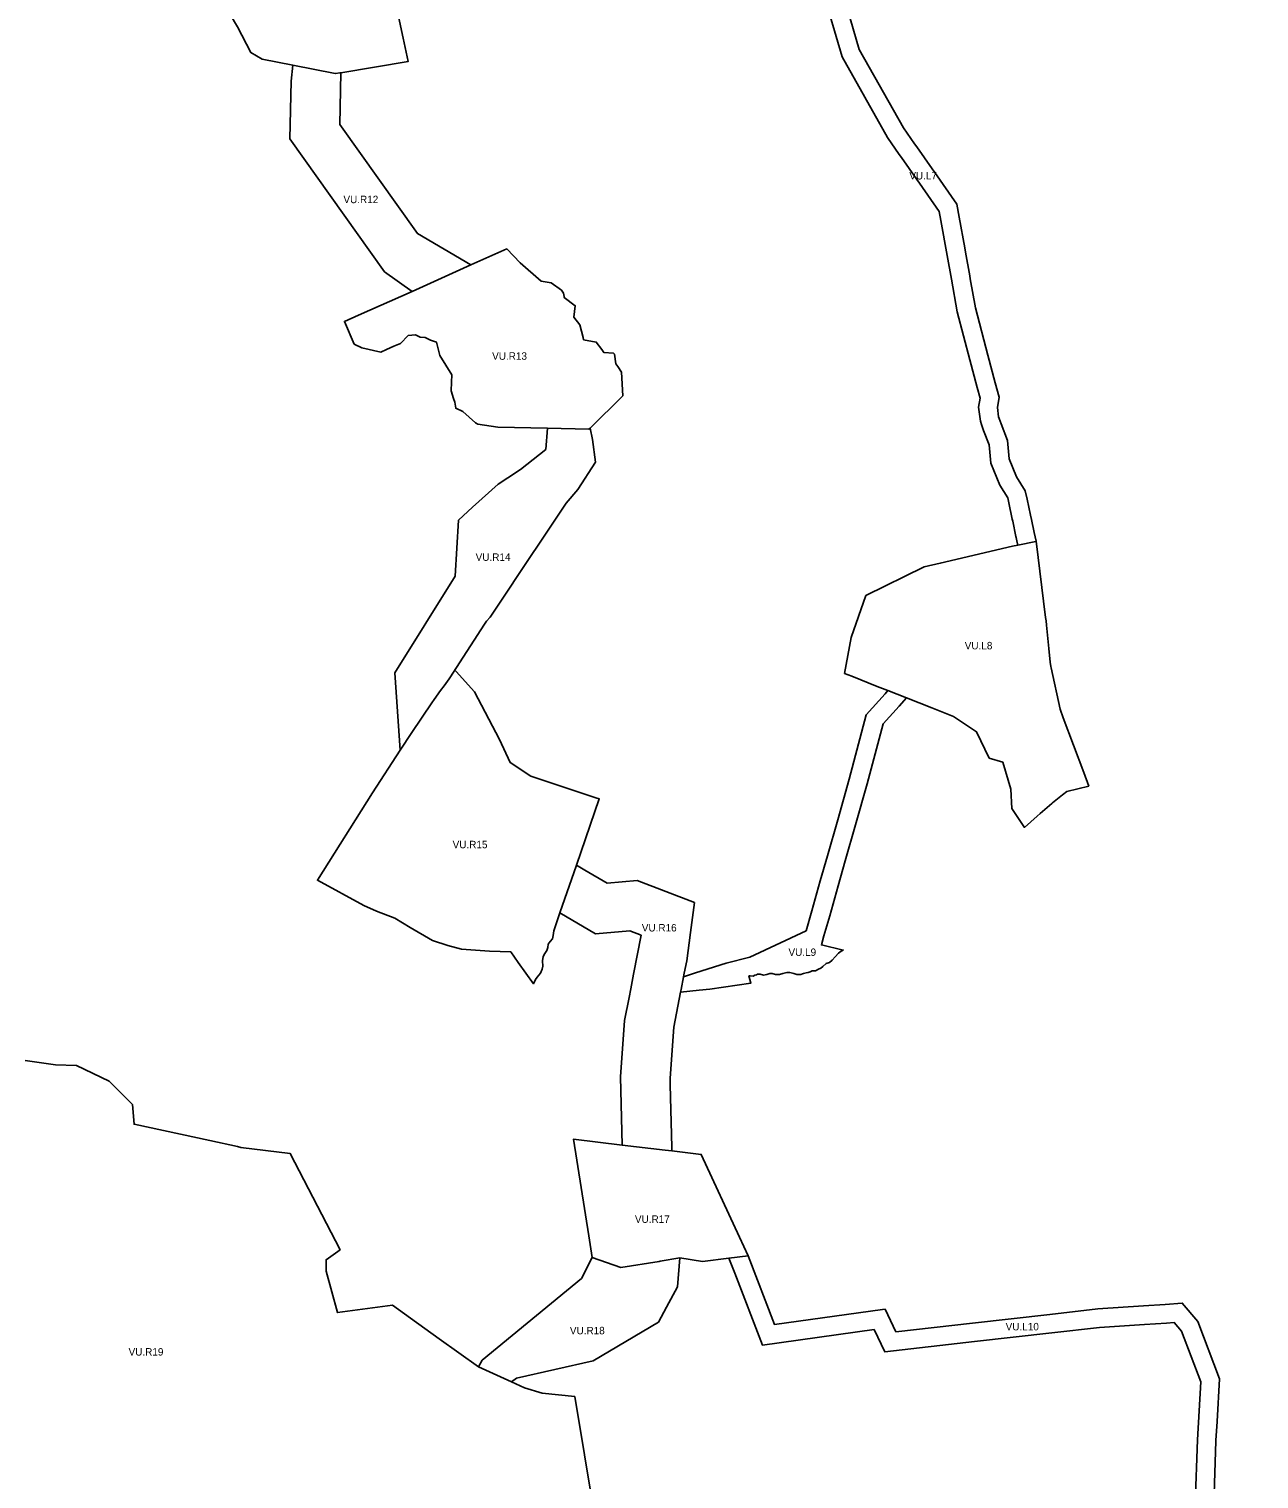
# Model space of a CAD drawing. Extents: x -439083 to -433688, y -1130252 to -1121189.
# Drawn here: x -435972 to -433988, y -1127489 to -1125151 of the extents above; entities that cross this region are included whole.
import ezdxf

# ---------------------------------------------------------------- set-up
doc = ezdxf.new("R2010")
doc.units = 0
doc.layers.add('Vrstva 28', color=7, linetype='Continuous')
doc.layers.add('Vrstva 31', color=7, linetype='Continuous')

msp = doc.modelspace()

# ---------------------------------------------------------------- linework, layer by layer
at = {"layer": 'Vrstva 28'}
for p, q in [((-435468.6, -1125221.4), (-435469.8, -1125221.5)), ((-435353.4, -1125573.9), (-435258.9, -1125531.3)), ((-435258.9, -1125531.3), (-435353.4, -1125573.9)), ((-435014, -1125742.5), (-435016.1, -1125704.4)), ((-435066.3, -1125794.7), (-435014, -1125742.5)), ((-435135.1, -1125794.5), (-435068.8, -1125796)), ((-435068.8, -1125796), (-435135.1, -1125794.5)), ((-435068.8, -1125796), (-435066.3, -1125794.7)), ((-435066.3, -1125794.7), (-435068.8, -1125796)), ((-434376.6, -1125982.9), (-434347.7, -1125977)), ((-434347.7, -1125977), (-434376.6, -1125982.9)), ((-434347.4, -1125976.8), (-434347.7, -1125977)), ((-434376.6, -1125982.9), (-434377, -1125983)), ((-434376.8, -1125983), (-434376.6, -1125982.9)), ((-435287.9, -1126189.6), (-435237.1, -1126110.7)), ((-435287.9, -1126189.6), (-435291.9, -1126195.5)), ((-435302.1, -1126209.8), (-435293.9, -1126198.6)), ((-434586.2, -1126217.7), (-434556.5, -1126229.4)), ((-434556.5, -1126229.4), (-434586.2, -1126217.7)), ((-435321.9, -1126237.1), (-435353.9, -1126285.4)), ((-435353.9, -1126285.4), (-435321.9, -1126237.1)), ((-435353.9, -1126285.4), (-435372.8, -1126313.9)), ((-435372.8, -1126313.9), (-435353.9, -1126285.4)), ((-435115.4, -1126576), (-435088.6, -1126499)), ((-435115.2, -1126576.2), (-435115.4, -1126576)), ((-434915.8, -1126679.1), (-434919.8, -1126699.6)), ((-434915.8, -1126679.1), (-434914.7, -1126673.3)), ((-434920.7, -1126704.1), (-434890.9, -1126700.8)), ((-434920.2, -1126701.9), (-434920.7, -1126704)), ((-434919.8, -1126699.6), (-434920.2, -1126701.9)), ((-434920.7, -1126704), (-434920.7, -1126704.1)), ((-435015.1, -1126950.3), (-434945.3, -1126958.6)), ((-434945.3, -1126958.6), (-435015.1, -1126950.3)), ((-434945.3, -1126958.6), (-434934.8, -1126959.8)), ((-434934.8, -1126959.8), (-434945.3, -1126958.6)), ((-435063.4, -1127131.5), (-435016.9, -1127148)), ((-435016.9, -1127148), (-435063.4, -1127131.5)), ((-435016.9, -1127148), (-434955.2, -1127137.9)), ((-434955.2, -1127137.9), (-434953.8, -1127137.6)), ((-434953.8, -1127137.6), (-434922.1, -1127132.4)), ((-434922.1, -1127132.4), (-434953.8, -1127137.6)), ((-434842.7, -1127132.6), (-434811.7, -1127128.8)), ((-434811.7, -1127128.8), (-434842.7, -1127132.6)), ((-435246.4, -1127308), (-435309.8, -1127262.9)), ((-435240.7, -1127297), (-435246.4, -1127308)), ((-435246.4, -1127308), (-435193.2, -1127332.3)), ((-435193.2, -1127332.3), (-435246.4, -1127308))]:
    msp.add_line(p, q, dxfattribs=at)
for points in [[(-435468.6, -1125221.4), (-435359.9, -1125203.1), (-435368.1, -1125165.7), (-435375.8, -1125130.7), (-435384.8, -1125101), (-435405.2, -1125057), (-435354.5, -1124861.6), (-435477.4, -1124902.8), (-435712.7, -1125017), (-435635.3, -1125147.3), (-435613.5, -1125189), (-435595.6, -1125199.5), (-435546.1, -1125209.4), (-435477.7, -1125222.9)], [(-434691.7, -1125087.6), (-434660.3, -1125195.8), (-434586.8, -1125326), (-434567.9, -1125353), (-434564.5, -1125358), (-434539.6, -1125393.6), (-434535.4, -1125399.6), (-434503.5, -1125445.3), (-434500.9, -1125459.8), (-434490.7, -1125516.1), (-434483.9, -1125554.2), (-434474.4, -1125607.1), (-434454.1, -1125684.3), (-434442.4, -1125729.1), (-434437.6, -1125746), (-434440, -1125760.7), (-434437.1, -1125783.2), (-434435.3, -1125788.6), (-434432.1, -1125798), (-434422.8, -1125821.5), (-434420.5, -1125851), (-434405.6, -1125886.6), (-434393, -1125906.9), (-434391.3, -1125914.9), (-434385.7, -1125941), (-434385, -1125944.6), (-434379.8, -1125968.9), (-434379.4, -1125970.7), (-434378.3, -1125975.9), (-434376.8, -1125983)], [(-434347.7, -1125977), (-434347.4, -1125976.8), (-434349, -1125969.6), (-434350.4, -1125962.7), (-434355, -1125941.5), (-434356.4, -1125934.7), (-434362, -1125908.7), (-434364.8, -1125895.6), (-434378.8, -1125872.8), (-434390.9, -1125843.9), (-434393.3, -1125814.6), (-434403.9, -1125787.6), (-434406.8, -1125778.9), (-434407.7, -1125776.4), (-434409.7, -1125761.2), (-434406.9, -1125744.3), (-434413.4, -1125721.2), (-434425.1, -1125676.7), (-434445, -1125600.6), (-434453.5, -1125553.9), (-434454.4, -1125548.9), (-434461.2, -1125510.8), (-434462.5, -1125503.9), (-434471.4, -1125454.4), (-434475.1, -1125433.5), (-434510.8, -1125382.4), (-434515, -1125376.4), (-434539.8, -1125340.8), (-434543.3, -1125335.9), (-434561.4, -1125310), (-434632.5, -1125184.1), (-434660.6, -1125087.1)], [(-435546.1, -1125209.4), (-435548.9, -1125234.9), (-435550.8, -1125327.8), (-435398.3, -1125542.3), (-435353.4, -1125573.9)], [(-435469.8, -1125221.5), (-435477.7, -1125222.9), (-435546.1, -1125209.4)], [(-435477.7, -1125222.9), (-435469.8, -1125221.5), (-435468.6, -1125221.4)], [(-435258.9, -1125531.3), (-435345.1, -1125480.7), (-435470.4, -1125304.9), (-435468.6, -1125221.4)], [(-435016.1, -1125704.4), (-435021.9, -1125695.3), (-435024.9, -1125690.5), (-435027.2, -1125675.2), (-435028.7, -1125673.7), (-435044.7, -1125672.4), (-435047.9, -1125667.8), (-435056.6, -1125655.7), (-435077, -1125651.9), (-435078, -1125648.1), (-435082.9, -1125628.1), (-435093, -1125615.4), (-435090.6, -1125597.1), (-435108.3, -1125584), (-435108.7, -1125582), (-435109.7, -1125577), (-435112.8, -1125571.9), (-435129.2, -1125560.1), (-435145.4, -1125557.6), (-435179.6, -1125527.8), (-435200.9, -1125505.6), (-435258.9, -1125531.3)], [(-435353.4, -1125573.9), (-435440.2, -1125612.5), (-435462.7, -1125622.5), (-435447.1, -1125659), (-435435, -1125665.2), (-435404.1, -1125671.8), (-435394.8, -1125667.6), (-435383, -1125662.4), (-435372.5, -1125657.8), (-435360.1, -1125645.3), (-435348.2, -1125644.2), (-435340.4, -1125647.8), (-435332.7, -1125648.4), (-435323.9, -1125652.5), (-435314.2, -1125655.9), (-435309.2, -1125677.4), (-435289.4, -1125708.7), (-435290.1, -1125720.3), (-435290.9, -1125734.5), (-435286.7, -1125746.9), (-435284.7, -1125752.8), (-435283.4, -1125762.5), (-435271.6, -1125767.6), (-435251.6, -1125785.8), (-435247.6, -1125788.2), (-435215.6, -1125793.1), (-435135.1, -1125794.5)], [(-435135.1, -1125794.5), (-435137.8, -1125828.7), (-435179.1, -1125861.1), (-435199.1, -1125874.6), (-435214.9, -1125884.9), (-435256.2, -1125922), (-435279, -1125943), (-435284.3, -1126033.2), (-435381.6, -1126189.2), (-435372.8, -1126313.9)], [(-435237.1, -1126110.7), (-435233.8, -1126105.5), (-435228, -1126099.4), (-435207.6, -1126068.8), (-435173.5, -1126017.6), (-435138.7, -1125965.6), (-435105.2, -1125915.3), (-435086.3, -1125893.5), (-435057.9, -1125849.2), (-435062.5, -1125812.8), (-435066.3, -1125794.7)], [(-434556.5, -1126229.4), (-434515.7, -1126245.5), (-434480.6, -1126259.4), (-434443.4, -1126284), (-434423, -1126326.4), (-434401, -1126333.2), (-434388.3, -1126376.7), (-434386.2, -1126407.7), (-434366.3, -1126438.1), (-434345.6, -1126420.1), (-434340.6, -1126415.8), (-434322.1, -1126399.7), (-434320.9, -1126398.6), (-434304.7, -1126385.8), (-434297.9, -1126380.4), (-434262.4, -1126371.5), (-434270.6, -1126349.6), (-434303.5, -1126261.6), (-434308.7, -1126247.7), (-434322.9, -1126180.8), (-434323.4, -1126178.5), (-434324.8, -1126172), (-434326.9, -1126149.7), (-434330.6, -1126112.1), (-434331.3, -1126105.1), (-434332, -1126099.7), (-434347.4, -1125976.9), (-434347.4, -1125976.8)], [(-434377, -1125983), (-434385.6, -1125984.8), (-434501.8, -1126012.2), (-434501.8, -1126012.4), (-434528.1, -1126018.3), (-434621.9, -1126064.2)], [(-434621.9, -1126064.2), (-434645.8, -1126132.2), (-434656.2, -1126189.8), (-434644.7, -1126194.5), (-434603.5, -1126210.8), (-434586.2, -1126217.7)], [(-435293.9, -1126198.6), (-435291.9, -1126195.5), (-435287.9, -1126189.6)], [(-435088.6, -1126499), (-435051.8, -1126392.1), (-435057.1, -1126390.5), (-435162.2, -1126355.6), (-435195.6, -1126333.8), (-435212.7, -1126296.3), (-435252.9, -1126219.7), (-435282.6, -1126186.9), (-435284.6, -1126184.7), (-435287.9, -1126189.6)], [(-435291.9, -1126195.5), (-435293.9, -1126198.6), (-435302.1, -1126209.8), (-435307.8, -1126217.7), (-435318.2, -1126232), (-435321.9, -1126237.1)], [(-435321.9, -1126237.1), (-435318.2, -1126232), (-435307.8, -1126217.7), (-435302.1, -1126209.8)], [(-434586.2, -1126217.7), (-434590.7, -1126222.7), (-434621.2, -1126256.8), (-434648.6, -1126360.2), (-434667.3, -1126426), (-434683.9, -1126483.8), (-434695.4, -1126524.4), (-434709, -1126572.5), (-434718.3, -1126604.8), (-434808.9, -1126647.6), (-434847.4, -1126657.1), (-434896.5, -1126672.9), (-434915.8, -1126679.1)], [(-434890.9, -1126700.8), (-434873.5, -1126699), (-434807.2, -1126689.1), (-434810.5, -1126677.6), (-434808.2, -1126677.6), (-434803.4, -1126678), (-434800.8, -1126676.7), (-434798.5, -1126675.7), (-434796.8, -1126675), (-434792.2, -1126675), (-434786.7, -1126676.2), (-434781.4, -1126675.6), (-434776.9, -1126673.9), (-434772.8, -1126673.9), (-434767.7, -1126675.6), (-434761.4, -1126675.6), (-434755.7, -1126673.5), (-434749.5, -1126672.2), (-434744.3, -1126672.2), (-434738.3, -1126673.5), (-434733.3, -1126675.5), (-434726.7, -1126675.5), (-434724, -1126674.3), (-434722.2, -1126673.9), (-434717.9, -1126672.7), (-434715, -1126672), (-434711.5, -1126671.1), (-434708.5, -1126669.7), (-434703.3, -1126669.2), (-434698.5, -1126666.9), (-434694.5, -1126664.9), (-434691.2, -1126662.7), (-434685.8, -1126657.8), (-434680.7, -1126655.9), (-434676, -1126652.2), (-434671.2, -1126646.9), (-434665.9, -1126640.9), (-434661.7, -1126637.8), (-434658.3, -1126635.9), (-434693.6, -1126627.8), (-434689.4, -1126613), (-434680.2, -1126580.7), (-434666.5, -1126532.6), (-434655, -1126492), (-434638.5, -1126434.2), (-434619.7, -1126368.1), (-434594, -1126271.4), (-434568.3, -1126242.7), (-434556.5, -1126229.4)], [(-435372.8, -1126313.9), (-435417.8, -1126382.5), (-435506.4, -1126523.4), (-435431.5, -1126564.3), (-435410.9, -1126573.1), (-435381.3, -1126584.6), (-435356.7, -1126599.8), (-435320.6, -1126620.7), (-435295.9, -1126628.4), (-435274.1, -1126634.7), (-435228.7, -1126637.7), (-435194.7, -1126638.7), (-435182.8, -1126656), (-435158.1, -1126690.3), (-435156.7, -1126688), (-435154.8, -1126683.2), (-435151.9, -1126679.5), (-435146.6, -1126673.3), (-435143.8, -1126667), (-435142.9, -1126662.1), (-435143.4, -1126653.3), (-435142.1, -1126646.2), (-435139.6, -1126641.6), (-435136.4, -1126636.9), (-435135, -1126631.9), (-435134.2, -1126626.7), (-435130.9, -1126622.4), (-435127.3, -1126617.6), (-435126, -1126612.4), (-435125.2, -1126605.2), (-435115.2, -1126576.2)], [(-435088.6, -1126499), (-435115.4, -1126576), (-435115.2, -1126576.2), (-435058, -1126609.8)], [(-434914.7, -1126673.3), (-434910.8, -1126653.6), (-434904.8, -1126607.6), (-434898.5, -1126559.3), (-434990.7, -1126524), (-435039.3, -1126528), (-435074.9, -1126507), (-435088.6, -1126499)], [(-435058, -1126609.8), (-435002.3, -1126605.2), (-434984.3, -1126612.1), (-434996.5, -1126674.9), (-435001.1, -1126698.6), (-435003.8, -1126712.6), (-435011, -1126749.5), (-435017.7, -1126840.5), (-435015.1, -1126950.3)], [(-434920.7, -1126704.1), (-434920.7, -1126704), (-434920.2, -1126701.9), (-434919.8, -1126699.6), (-434915.8, -1126679.1)], [(-434934.8, -1126959.8), (-434935, -1126953.6), (-434937.4, -1126853.5), (-434937.7, -1126842.4), (-434931.6, -1126760.1), (-434920.7, -1126704.1)], [(-435309.8, -1127262.9), (-435356.4, -1127229.4), (-435385.3, -1127208.6), (-435474.1, -1127220.6), (-435492.4, -1127153.6), (-435492.4, -1127135.3), (-435469.8, -1127119.1), (-435550.3, -1126964), (-435629.9, -1126954.1), (-435635.5, -1126952.8), (-435680, -1126942.8), (-435802, -1126916.7), (-435804.8, -1126885), (-435842.2, -1126847.6), (-435894.8, -1126821.9), (-435928.9, -1126820.8), (-435977.5, -1126813.8)], [(-435015.1, -1126950.3), (-435093.5, -1126940.9), (-435068.9, -1127096.9), (-435063.4, -1127131.5)], [(-434811.7, -1127128.8), (-434825.5, -1127099.1), (-434887.4, -1126965.5), (-434934.8, -1126959.8)], [(-435063.4, -1127131.5), (-435080.5, -1127165.4), (-435240.7, -1127297)], [(-435193.2, -1127332.3), (-435185.2, -1127326), (-435061.6, -1127298.2), (-434956.4, -1127235.9), (-434943.3, -1127211.6), (-434925.8, -1127179.2), (-434922.1, -1127132.4)], [(-434953.8, -1127137.6), (-434955.2, -1127137.9), (-435016.9, -1127148)], [(-434922.1, -1127132.4), (-434885.6, -1127137.9), (-434842.7, -1127132.6)], [(-434842.7, -1127132.6), (-434833.1, -1127156.7), (-434788.7, -1127272.9), (-434608.5, -1127247.6), (-434591.4, -1127283.7), (-434446.6, -1127267.3), (-434321.7, -1127253.2), (-434245.1, -1127244.3), (-434172.3, -1127239.5), (-434137, -1127237.6), (-434124.4, -1127236.5), (-434112.6, -1127250.3), (-434081.6, -1127332.1), (-434087.1, -1127425.4), (-434090.7, -1127529.7), (-434089.3, -1127606.6), (-434054.8, -1127717.1), (-434031.6, -1127785), (-434006.2, -1127862.5), (-433994.2, -1127899.2), (-433989.5, -1127913.4), (-433988.2, -1127917.4), (-433987.8, -1127918.9)], [(-434060.6, -1127529.9), (-434057.2, -1127428), (-434057.2, -1127426.8), (-434055.4, -1127396.2), (-434051.3, -1127327.5), (-434086.4, -1127234.9), (-434111.6, -1127205.2), (-434139.1, -1127207.7), (-434174.1, -1127209.5), (-434247.8, -1127214.4), (-434325.1, -1127223.4), (-434449.9, -1127237.5), (-434573.5, -1127251.5), (-434590.9, -1127214.8), (-434594.8, -1127215.3), (-434769.2, -1127239.9), (-434811.7, -1127128.8)], [(-435527.7, -1128107.5), (-435503.6, -1128100.1), (-435481.7, -1128093.4), (-435456, -1128108.2), (-435443.3, -1128113.4), (-435375.9, -1128110.2), (-435285.1, -1128096.6), (-435212.6, -1128028.6), (-435176.3, -1127978.7), (-435117.3, -1127878.9), (-435115.6, -1127869.2), (-435072.9, -1127853.8), (-435027.1, -1127828.4), (-434988.3, -1127772), (-435019.3, -1127755.1), (-435032.7, -1127724.7), (-435044.7, -1127638), (-435091.3, -1127356), (-435144.1, -1127350.3), (-435172.3, -1127341.9), (-435193.2, -1127332.3), (-435193.2, -1127332.3)]]:
    msp.add_lwpolyline(points, dxfattribs=at)

# ---------------------------------------------------------------- texts
at = {"layer": 'Vrstva 31'}
for s, p in [('VU.L7', (-434551.8, -1125393.5)), ('VU.R12', (-435464.4, -1125431.7)), ('VU.R13', (-435224.6, -1125684.2)), ('VU.R14', (-435251.2, -1126008.4)), ('VU.L8', (-434462.4, -1126151.1)), ('VU.R15', (-435288.3, -1126471.8)), ('VU.R16', (-434983.2, -1126606)), ('VU.L9', (-434746.7, -1126645.4)), ('VU.R17', (-434994.3, -1127075.8)), ('VU.L10', (-434396.4, -1127249.1)), ('VU.R18', (-435099.2, -1127255.5)), ('VU.R19', (-435810.9, -1127289.8))]:
    msp.add_text(s, height=12, dxfattribs=at).set_placement(p)

doc.saveas('drawing.dxf')
